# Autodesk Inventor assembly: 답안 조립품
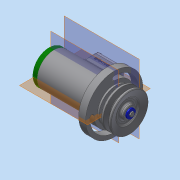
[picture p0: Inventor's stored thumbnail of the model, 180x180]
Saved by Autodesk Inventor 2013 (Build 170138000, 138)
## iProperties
Created: 2017-05
Part Number: 답안 조립품
Document SubType Name: Assembly
Designer: dgall
Author: dgall
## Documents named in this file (20)
- C:\Users\dgall\Desktop\470507V1019\답안 조립품.iam
- C:\Users\dgall\Desktop\470507V1019\본체.ipt
- C:\Users\dgall\Desktop\470507V1019\V-벨트풀리.ipt
- C:\Users\dgall\Desktop\470507V1019\너트 M10.ipt
- C:\Users\dgall\Desktop\470507V1019\멈춤링 15 x 1.ipt
- C:\Users\dgall\Desktop\470507V1019\멈춤링 35x1.6.ipt
- C:\Users\dgall\Desktop\470507V1019\베어링 15 x 35 x 11.ipt
- C:\Users\dgall\Desktop\470507V1019\볼트 M4 x 10.ipt
- C:\Users\dgall\Desktop\470507V1019\부시1.ipt
- C:\Users\dgall\Desktop\470507V1019\부시2.ipt
- C:\Users\dgall\Desktop\470507V1019\사이드 커버.ipt
- 사이드 커버.ipt
- C:\Users\dgall\Desktop\470507V1019\십자볼트 M3 x 10.ipt
- C:\Users\dgall\Desktop\470507V1019\오일 실 15 25 7.ipt
- C:\Users\dgall\Desktop\470507V1019\와셔 3x6.ipt
- C:\Users\dgall\Desktop\470507V1019\와셔 4x16.ipt
- C:\Users\dgall\Desktop\470507V1019\와셔 10x21.ipt
- C:\Users\dgall\Desktop\470507V1019\축.ipt
- C:\Users\dgall\Desktop\470507V1019\키 4 x 4 x 18.ipt
- C:\Users\dgall\Desktop\470507V1019\탑 커버.ipt
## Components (2 placed, 2 different names)
1. V-벨트풀리:1
2. ISO 4017 M4 x 10:1
